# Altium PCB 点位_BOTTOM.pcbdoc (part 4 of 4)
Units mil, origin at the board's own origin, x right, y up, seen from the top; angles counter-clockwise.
Board outline 5102.8 x 4152 mil, 8 copper layers (Top Layer, GND1, 内层2, VCC, 内层4, Inner5, GND2, Bottom Layer); 209 components, 325 nets, 527 pads, 1119 vias.
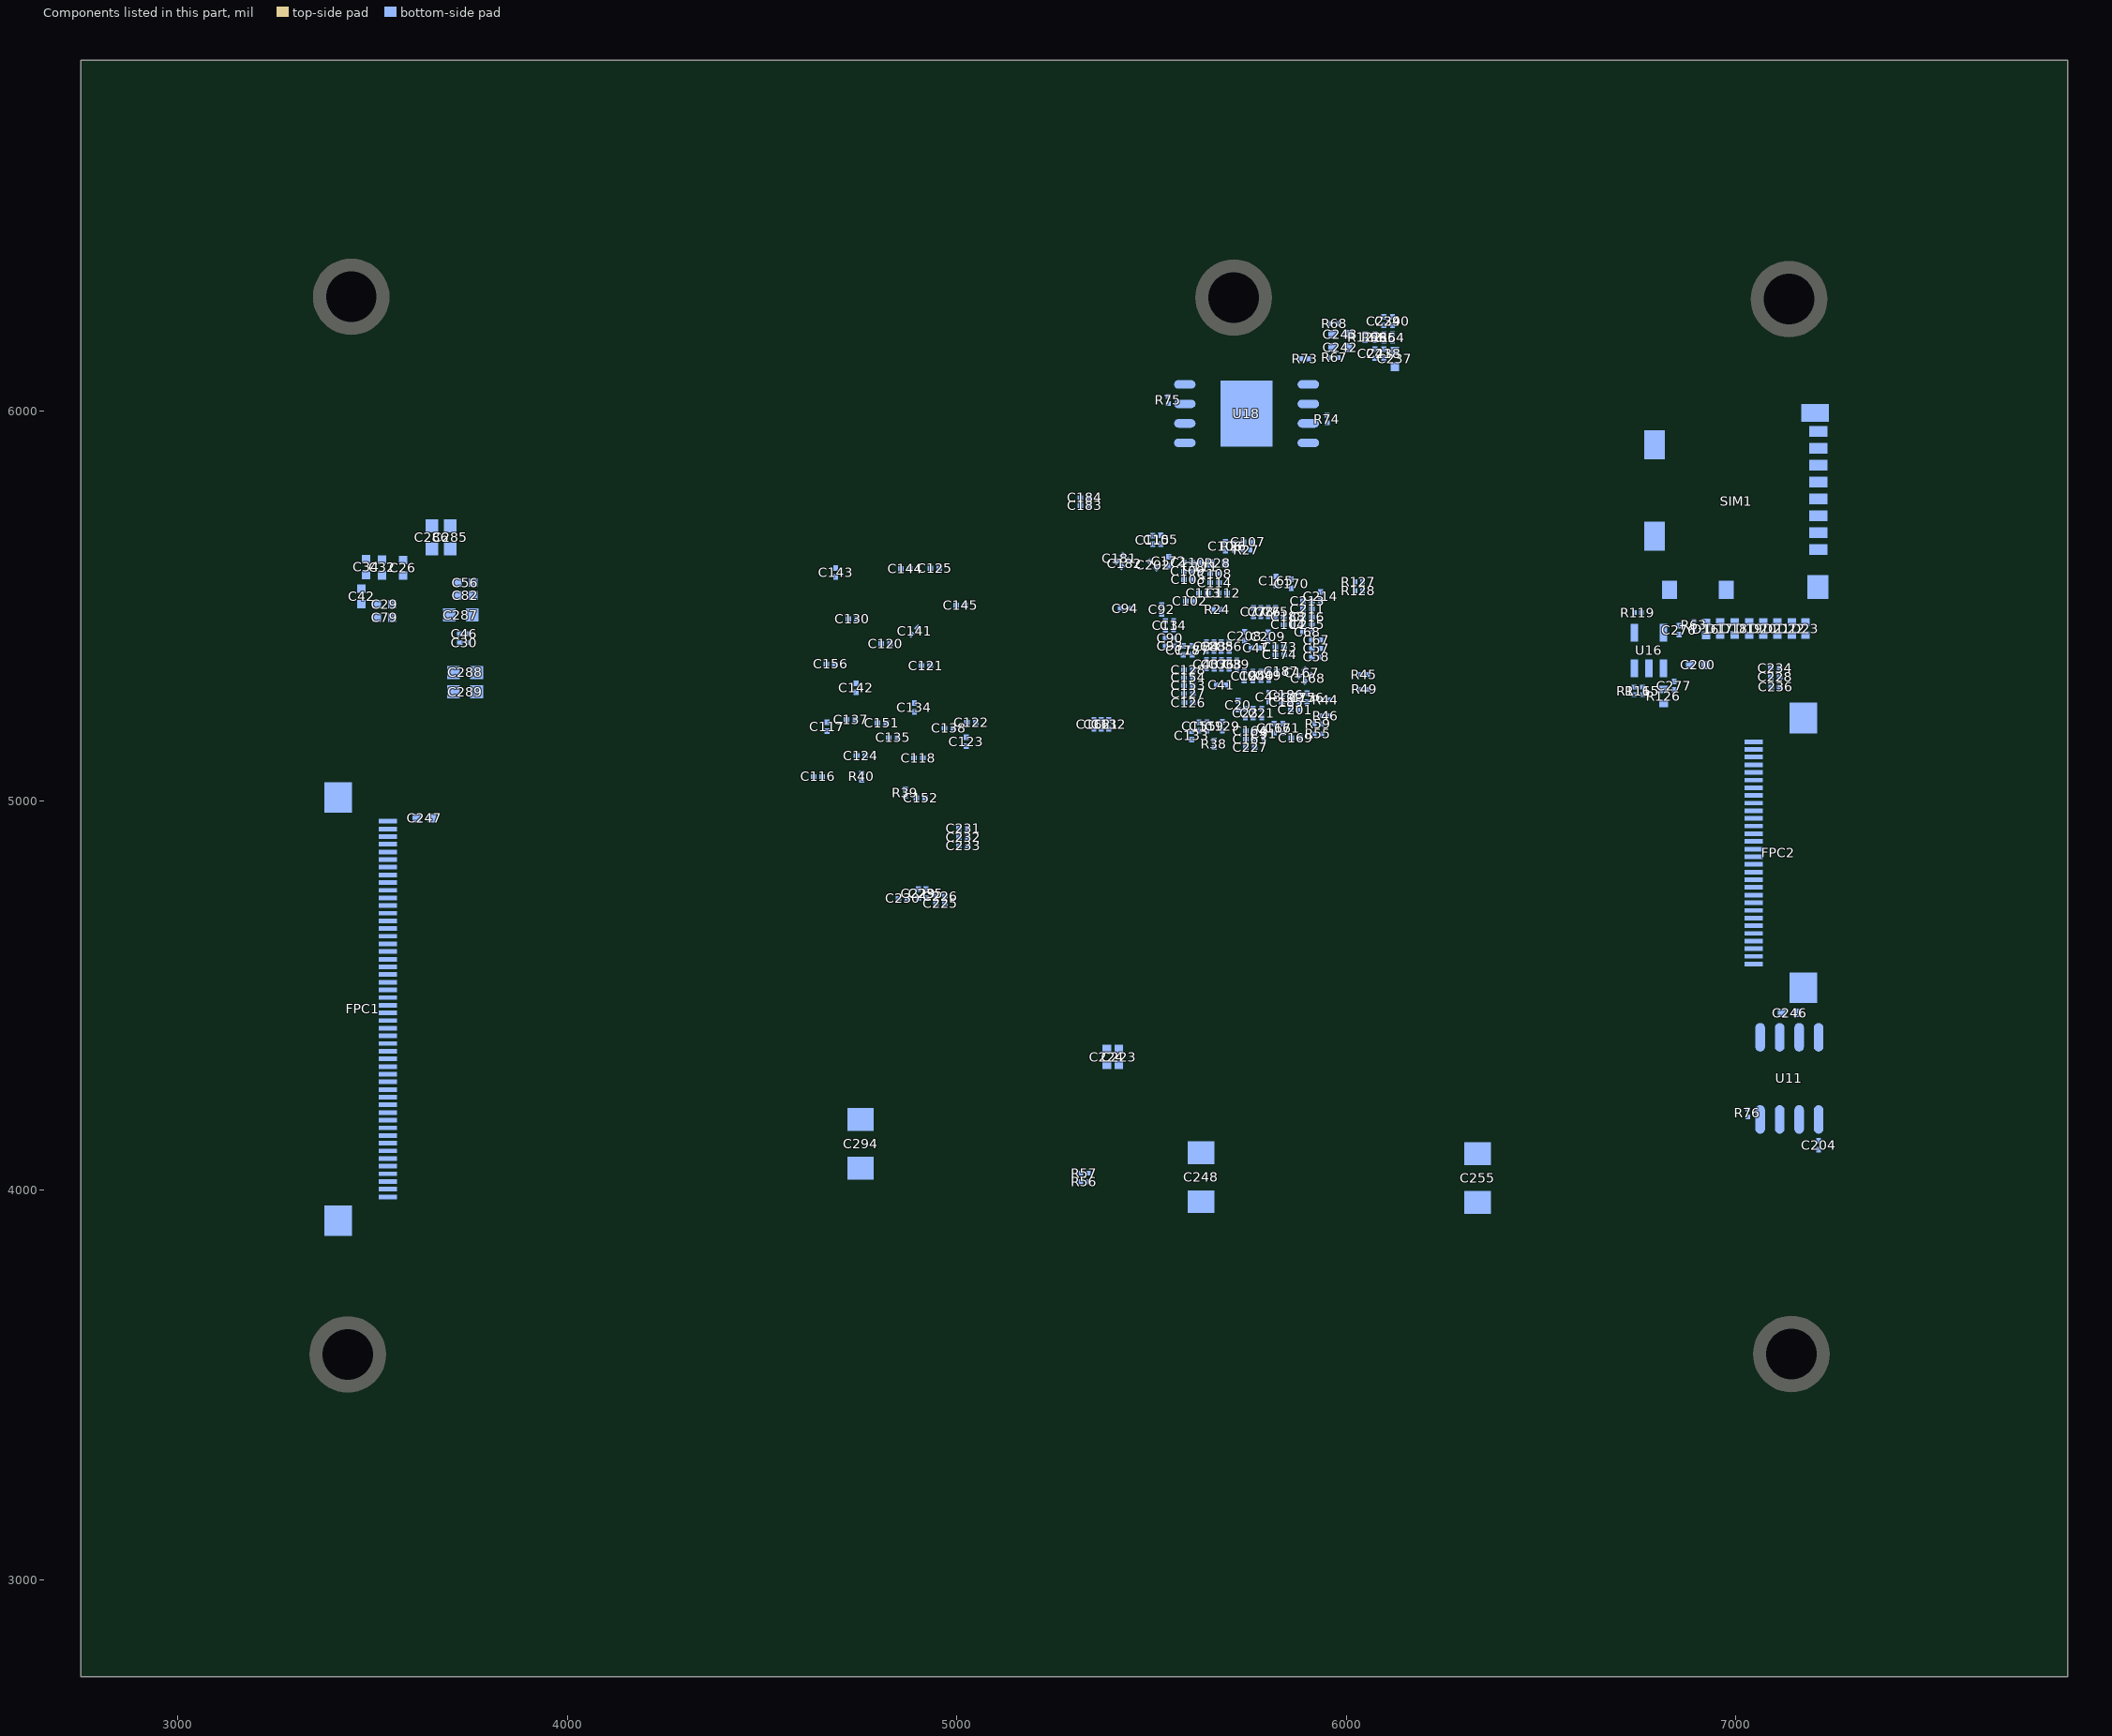
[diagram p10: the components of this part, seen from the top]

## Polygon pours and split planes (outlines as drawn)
GND on 内层2 (solid, remove dead copper): 3007.34,3040 7565.34,3040 7565.34,6640 3007.34,6640
GND on GND1 (solid, remove dead copper): 3000,3052 7558,3052 7558,6652 3000,6652
GND on VCC (solid, remove dead copper): 3012.8,3034 7570.8,3034 7570.8,6634 3012.8,6634
GND on 内层4 (solid, remove dead copper): 3020.8,3025 7578.8,3025 7578.8,6625 3020.8,6625
GND on Inner5 (solid, remove dead copper): 3027.27,3017.38 7585.27,3017.38 7585.27,6617.38 3027.27,6617.38
GND on GND2 (solid, remove dead copper): 3034.8,3010 7592.8,3010 7592.8,6610 3034.8,6610
GND on Bottom Layer (solid, remove dead copper, pour order 36): 3044.8,3000 7602.8,3000 7602.8,6600 3044.8,6600
GND on GND1 (solid, remove dead copper): 5704.72,5249.97 5648.72,5249.97 5636.72,5261.97 5636.72,5357.97 5604.72,5389.97 5361.72,5389.97 5107.72,5643.97 4598.72,5643.97 4578.72,5623.97 4578.72,5014.97 4694.72,4898.97 5650.72,4898.97 5715.72,4963.97 5715.72,5238.97
GND on GND2 (solid, remove dead copper): 5704.24,5250.47 5648.24,5250.47 5636.24,5262.47 5636.24,5358.47 5604.24,5390.47 5361.24,5390.47 5107.24,5644.47 4598.24,5644.47 4578.24,5624.47 4578.24,5015.47 4694.24,4899.47 5650.24,4899.47 5715.24,4964.47 5715.24,5239.47
GND on GND1 (solid, remove dead copper): 5704.66,5251.03 5648.66,5251.03 5636.66,5263.03 5636.66,5359.03 5604.66,5391.03 5361.66,5391.03 5107.66,5645.03 4598.66,5645.03 4578.66,5625.03 4578.66,5016.03 4694.66,4900.03 5650.66,4900.03 5715.66,4965.03 5715.66,5240.03
GND on VCC (solid, remove dead copper): 5705.22,5250.47 5649.22,5250.47 5637.22,5262.47 5637.22,5358.47 5605.22,5390.47 5362.22,5390.47 5108.22,5644.47 4599.22,5644.47 4579.22,5624.47 4579.22,5015.47 4695.22,4899.47 5651.22,4899.47 5716.22,4964.47 5716.22,5239.47
DCDC3 on 内层4 (solid, remove dead copper): 5704.54,5249.47 5648.54,5249.47 5636.54,5261.47 5636.54,5357.47 5616.54,5377.47 5366.54,5377.47 5102.54,5641.47 4596.54,5641.47 4578.54,5623.47 4578.54,5014.47 4694.54,4898.47 5650.54,4898.47 5715.54,4963.47 5715.54,5238.47
BLDO2 on Bottom Layer (solid, remove dead copper, pour order 10): 5023.72,4994.97 5080.19,5051.44 5080.19,5582.5 5026.72,5635.97 4634.21,5635.97 4582.46,5584.22 4582.46,5040.29 4627.77,4994.97
323-DCDC1/2 on 内层2 (solid, remove dead copper): 5657.73,5366.51 5657.73,5263.51 5682.23,5239 5775.8,5239 5789.8,5253 5789.8,5444.25 5390.05,5844 4587.8,5844 4392.8,5649 4392.8,5534 4128.8,5270 4128.8,5083 4178.8,5033 4235.8,5033 4318.8,5116 4318.8,5220 4552.8,5454 4552.8,5597 4617.8,5662 5196.8,5662 5470.8,5388 5636.23,5388
PS on 内层2 (solid, remove dead copper): 3585.81,5664.28 3834.15,5664.28 3902.8,5595.63 3902.8,5393 4079.8,5216 4079.8,5080 4047.8,5048 3919.8,5048 3723.8,5244 3526.8,5244 3445.8,5325 3445.8,5611.07 3488.27,5653.53 3575.06,5653.53
323-DCDC3 on VCC (solid, remove dead copper): 5715.8,5464 5715.8,5425 5695.8,5405 5585.8,5405 5584.8,5406 5377.8,5406 5125.8,5658 4571.8,5658 4196.51,5282.71 4031.64,5282.71 3979.8,5334.55 3979.8,5395 4068.8,5484 4176.8,5484 4518.8,5826 5197.63,5826 5510.68,5512.95 5666.85,5512.95
DCDC3 on 内层4 (solid, remove dead copper): 3730.37,5739 3730.37,5637.28 3748.65,5619 3827.8,5619 3909.8,5537 3909.8,5502 4014.84,5396.97 4590.72,5396.97 4659.47,5465.72 4659.47,5641 4092.8,5641 3973.8,5760 3882.8,5760 3850.8,5792 3783.37,5792
DCDC2 on 内层4 (solid, remove dead copper): 5625.8,5411.39 5625.8,5413 5370.8,5413 5114.8,5669 4108.8,5669 3983.8,5794 3892.8,5794 3867.8,5819 3732.8,5819 3684.8,5771 3684.8,5725 3667.8,5708 3558.8,5708 3532.8,5734 3532.8,5840 3623.8,5931 4126.31,5931 4220.31,5837 5450.8,5837 5889.8,5398 5912.8,5398 5924.8,5386 5924.8,5350 5830.8,5256 5805.8,5256 5794.8,5267 5773.8,5267 5763.8,5277 5763.8,5318.66 5753.71,5328.76 5708.43,5328.76
DCDC1 on Inner5 (solid, remove dead copper): 5729.8,5331 5729.8,5280 5713.8,5264 5674.77,5264 5641.8,5296.96 5641.8,5350.19 5579.4,5412.59 5393.21,5412.59 5140.8,5665 4605.8,5665 4333.8,5393 4029.8,5393 3856.8,5220 3767.06,5220 3723.06,5264 3723.06,5369.09 3914.98,5561 4191.8,5561 4496.8,5866 5117.8,5866 5227.8,5756 5370.45,5756 5728.8,5397.65 5728.8,5332
GND on Bottom Layer (solid, remove dead copper, pour order 38): 5900.8,6146 5900.8,6139 5902.8,6137 5902.8,6135 5905.8,6132 5905.8,6141

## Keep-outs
内层2:
  region: 5628.17,4988.43 5556.72,4916.97 4948.89,4916.97 4850.39,5015.47 4613.16,5015.47 4610.9,5017.73 4610.9,5604.71 4632.16,5625.97 5132.72,5625.97 5366.72,5391.97 5398.72,5391.97 5480.72,5309.97 5568.72,5309.97 5628.17,5250.52
Inner5:
  region: 5701.72,5157.93 5681.41,5178.25 5479.15,5178.25 5463.42,5193.97 5463.42,5235.24 5471.66,5243.47 5531.56,5243.47 5560.72,5272.63 5560.72,5305.97 5517.44,5349.26 5504.25,5349.26 5465.53,5387.97 5367.72,5387.97 5115.72,5639.97 4620.84,5639.97 4582.09,5601.22 4582.09,5497.35 4579.72,5494.97 4579.72,5057.97 4719.72,4917.97 5645.17,4917.97 5701.72,4974.52
Board Outline Layer:
  lines w10: 3321.8,3578.11 ccw(c3439.91,3578.11) 3439.91,3460 7140.7,3460 ccw(c7140.7,3578.11) 7258.81,3578.11 7258.81,6294.65 ccw(c7140.7,6294.65) 7140.7,6412.76 3439.91,6412.76 ccw(c3439.91,6294.65) 3321.8,6294.65 3321.8,3578.11
Multi-Layer:
  region: 5837.51,4256.39 6050.11,4256.39 6167.34,4139.16 6281.8,4139.16 6281.8,3458.89 5651.91,3458.89 5651.8,3459 5651.8,4139.16 5720.28,4139.16
  region: 6555.76,4255.69 6768.36,4255.69 6885.59,4138.46 7000.05,4138.46 7000.05,3458.19 6370.16,3458.19 6370.05,3458.31 6370.05,4138.46 6438.53,4138.46

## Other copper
内层2:
  drawing of 214 lines, arcs and shapes, not listed
VCC:
  region net GM1_DVDDRG: 3510.49,5559.03 3467.45,5516 3447.8,5516 3427.8,5536 3427.8,5558.59 3464.22,5595 3496.73,5595 3510.49,5581.24
  region net ALDO3: 3535.27,5320.46 3531.03,5324.7 3530.42,5324.18 3529.75,5323.78 3529.04,5323.47 3528.29,5323.25 3527.51,5323.09 3525.9,5322.91 3525.08,5322.86 3533.43,5314.51 3533.56,5316.14 3533.66,5316.94 3533.82,5317.72 3534.04,5318.47 3534.35,5319.18 3534.75,5319.85
  region net USB0-DP: 6306.3,5223.37 6301.3,5223.37 6301.23,5222.49 6301.01,5221.75 6300.67,5221.12 6300.24,5220.55 6299.15,5219.47 6297.9,5218.21 6309.71,5218.21 6308.46,5219.47 6307.37,5220.55 6306.93,5221.12 6306.6,5221.75 6306.38,5222.49
  region net USB0-DM: 6286.3,5220.72 6281.3,5220.72 6281.23,5219.82 6281.01,5219.04 6280.67,5218.35 6280.24,5217.72 6279.72,5217.12 6277.9,5215.21 6289.71,5215.21 6287.88,5217.12 6287.37,5217.72 6286.93,5218.35 6286.6,5219.04 6286.38,5219.82
  region net GM1_DVDDRG: 6816.52,4253 6816.52,4263 6814.24,4262.9 6813.56,4262.9 6812.9,4262.97 6812.27,4263.14 6811.64,4263.44 6811.01,4263.91 6811.01,4252.09 6811.64,4252.56 6812.27,4252.86 6812.9,4253.03 6813.56,4253.1 6814.24,4253.1
  region net FEL: 5946.6,5398.16 5946.6,5392.16 5947.4,5392.1 5948.16,5391.91 5948.88,5391.63 5949.56,5391.25 5950.22,5390.81 5951.49,5389.8 5952.11,5389.26 5952.11,5401.07 5950.87,5400 5950.22,5399.51 5949.56,5399.07 5948.88,5398.7 5948.16,5398.41 5947.4,5398.23
  region net PE12: 6060.81,5761.83 6063.64,5759.01 6064.4,5759.65 6065.14,5760.04 6065.88,5760.23 6066.64,5760.29 6068.31,5760.18 6069.25,5760.13 6070.3,5760.14 6061.94,5768.49 6061.93,5767.45 6062.05,5765.64 6062.09,5764.84 6062.08,5764.46 6062.04,5764.08 6061.96,5763.71 6061.84,5763.34 6061.67,5762.97 6061.45,5762.6 6061.16,5762.22
  region net PE8: 6149.81,5760.83 6152.64,5758.01 6153.4,5758.65 6154.14,5759.04 6154.88,5759.23 6155.64,5759.29 6157.31,5759.18 6158.25,5759.13 6159.3,5759.14 6150.94,5767.49 6150.93,5766.45 6151.05,5764.64 6151.09,5763.84 6151.08,5763.46 6151.04,5763.08 6150.96,5762.71 6150.84,5762.34 6150.67,5761.97 6150.45,5761.6 6150.16,5761.22
  region net PE7: 6178.8,5757.28 6182.8,5757.28 6182.89,5758.27 6183.14,5759.08 6183.52,5759.74 6184.02,5760.31 6185.27,5761.41 6185.98,5762.04 6186.71,5762.79 6174.9,5762.79 6175.63,5762.04 6176.99,5760.85 6177.58,5760.31 6177.85,5760.03 6178.08,5759.74 6178.29,5759.42 6178.47,5759.08 6178.61,5758.7 6178.72,5758.27 6178.78,5757.8
  region net PE5: 6129.08,5712 6129.08,5708 6129.75,5707.96 6130.47,5707.86 6131.23,5707.69 6132,5707.46 6132.74,5707.18 6133.44,5706.86 6134.07,5706.49 6134.6,5706.09 6134.6,5717.91 6133.97,5717.23 6132.7,5715.39 6132.05,5714.4 6131.37,5713.48 6130.65,5712.72 6129.89,5712.19
  region net PE6: 6153.81,5704.83 6156.64,5702.01 6157.19,5702.47 6157.82,5702.88 6158.52,5703.24 6159.26,5703.53 6160.03,5703.77 6160.81,5703.95 6161.57,5704.07 6162.3,5704.14 6153.94,5712.49 6153.96,5711.65 6154.36,5708.44 6154.44,5707.35 6154.41,5706.35 6154.22,5705.49
  region net PE1: 6176.64,5720.99 6173.81,5718.17 6174.45,5717.4 6174.84,5716.66 6175.04,5715.92 6175.09,5715.16 6174.98,5713.5 6174.93,5712.55 6174.94,5711.51 6183.3,5719.86 6182.25,5719.87 6180.44,5719.75 6179.64,5719.71 6179.26,5719.73 6178.88,5719.77 6178.51,5719.84 6178.14,5719.96 6177.77,5720.13 6177.4,5720.35 6177.02,5720.64
  region net CLDO3: 7116.92,5497.44 7109.85,5504.52 7108.31,5502.83 7107.82,5502.35 7107.31,5501.93 7106.74,5501.6 7106.08,5501.37 7105.31,5501.26 7113.66,5492.91 7113.78,5493.68 7114.01,5494.34 7114.34,5494.91 7114.75,5495.42 7115.23,5495.9
  region net GM1_DVDDRG: 7014.08,4159 7014.08,4149 7016.37,4149.1 7017.05,4149.1 7017.7,4149.03 7018.34,4148.86 7018.97,4148.56 7019.6,4148.09 7019.6,4159.91 7018.97,4159.44 7018.34,4159.14 7017.7,4158.97 7017.05,4158.9 7016.37,4158.9
  region net GM1_DVDDRG: 3499.08,5698.88 3499.08,5692.88 3499.88,5692.69 3500.64,5692.18 3501.36,5691.43 3502.04,5690.53 3503.98,5687.76 3504.59,5687.09 3504.59,5698.91 3503.88,5698.38 3503.25,5698.14 3502.67,5698.1 3502.1,5698.21 3500.81,5698.63 3500.02,5698.81
  region net AP-RESET: 3958.8,5064.28 3964.8,5064.28 3964.87,5065.08 3965.05,5065.84 3965.34,5066.55 3965.71,5067.24 3966.15,5067.9 3967.17,5069.17 3967.71,5069.79 3955.9,5069.79 3956.96,5068.54 3957.46,5067.9 3957.9,5067.24 3958.27,5066.55 3958.55,5065.84 3958.74,5065.08
  region net USB0-DP: 6697.04,6014.77 6700.57,6011.23 6701.23,6011.79 6701.87,6012.12 6702.51,6012.28 6703.15,6012.31 6704.57,6012.19 6705.39,6012.13 6706.3,6012.14 6697.94,6020.49 6697.93,6019.58 6698.07,6018.03 6698.11,6017.35 6698.08,6016.7 6697.92,6016.07 6697.59,6015.43
  region net USB0-DM: 6688.04,6011.23 6691.57,6014.77 6691.02,6015.43 6690.68,6016.07 6690.53,6016.7 6690.49,6017.35 6690.62,6018.77 6690.67,6019.58 6690.66,6020.49 6682.31,6012.14 6683.22,6012.13 6684.77,6012.26 6685.45,6012.31 6686.1,6012.28 6686.73,6012.12 6687.37,6011.79
  region net GM1_DVDDRG: 5292.8,4480.31 5302.8,4480.31 5302.69,4482.59 5302.69,4483.27 5302.76,4483.92 5302.93,4484.55 5303.23,4485.18 5303.69,4485.81 5291.92,4485.81 5292.38,4485.18 5292.68,4484.55 5292.85,4483.92 5292.92,4483.27 5292.91,4482.59
  region net VDD-DNRFB: 5631.26,5430.19 5638.33,5423.12 5639.87,5424.81 5640.34,5425.29 5640.85,5425.7 5641.42,5426.03 5642.07,5426.26 5642.85,5426.38 5634.52,5434.7 5634.4,5433.93 5634.17,5433.28 5633.85,5432.71 5633.43,5432.2 5632.95,5431.73
  region net VDD-DNRFB: 3936.9,5272.02 3929.82,5279.09 3928.29,5277.4 3927.81,5276.92 3927.31,5276.51 3926.74,5276.18 3926.08,5275.95 3925.31,5275.83 3933.64,5267.51 3933.75,5268.28 3933.98,5268.94 3934.31,5269.5 3934.72,5270.01 3935.2,5270.49
  region net CLDO3: 5566.49,6055.13 5559.42,6062.2 5557.88,6060.51 5557.41,6060.02 5556.9,6059.61 5556.33,6059.28 5555.68,6059.05 5554.91,6058.94 5563.23,6050.61 5563.35,6051.38 5563.58,6052.04 5563.91,6052.61 5564.32,6053.11 5564.8,6053.59
  region net AP-RESET: 3588.3,5402.31 3593.3,5402.31 3593.33,5402.89 3593.4,5403.4 3593.52,5403.84 3593.68,5404.22 3593.88,5404.56 3594.11,5404.85 3594.38,5405.12 3594.67,5405.37 3595.7,5406.1 3596.47,5406.66 3596.87,5406.99 3597.28,5407.37 3597.69,5407.81 3585.92,5407.81 3586.36,5407.26 3586.79,5406.63 3587.2,5405.95 3587.56,5405.23 3587.86,5404.49 3588.1,5403.74 3588.25,5403.01
  region net AP-NMI: 3609.8,5401.31 3615.8,5401.31 3615.96,5402.02 3616.39,5402.76 3617.03,5403.5 3617.79,5404.23 3620.13,5406.25 3620.69,5406.81 3608.92,5406.81 3609.38,5406.18 3609.68,5405.55 3609.85,5404.92 3609.92,5404.27 3609.91,5403.59
  region net AP-NMI: 3608.66,5420.97 3605.83,5418.14 3606.47,5417.38 3606.86,5416.64 3607.06,5415.9 3607.11,5415.15 3607.01,5413.49 3606.95,5412.55 3606.97,5411.51 3615.29,5419.83 3614.25,5419.85 3612.45,5419.73 3611.66,5419.69 3611.27,5419.71 3610.9,5419.75 3610.53,5419.82 3610.16,5419.94 3609.79,5420.11 3609.42,5420.33 3609.05,5420.62
  region net AP-NMI: 3610.83,5582.86 3613.66,5580.03 3614.42,5580.67 3615.16,5581.06 3615.9,5581.25 3616.66,5581.31 3618.31,5581.2 3619.25,5581.15 3620.29,5581.17 3611.97,5589.49 3611.95,5588.45 3612.08,5586.65 3612.11,5585.85 3612.1,5585.47 3612.06,5585.1 3611.98,5584.73 3611.86,5584.36 3611.69,5583.99 3611.47,5583.62 3611.19,5583.24
  region net ALDO3: 3824.87,5419.68 3820.62,5415.44 3821.14,5414.83 3821.54,5414.16 3821.85,5413.46 3822.07,5412.71 3822.23,5411.93 3822.41,5410.33 3822.47,5409.51 3830.79,5417.83 3829.17,5417.96 3828.37,5418.07 3827.59,5418.23 3826.85,5418.45 3826.14,5418.76 3825.48,5419.16
  region net AP-RESET: 3886.12,5202.5 3886.12,5197.5 3886.75,5197.57 3887.46,5197.74 3889.01,5198.19 3889.77,5198.37 3890.48,5198.45 3891.11,5198.38 3891.61,5198.11 3891.61,5209.89 3891.23,5209.5 3890.89,5209.04 3890.57,5208.52 3889.97,5207.36 3888.83,5204.91 3888.53,5204.35 3888.21,5203.84 3887.86,5203.39 3887.48,5203.02 3887.07,5202.74 3886.61,5202.56
  region net FEL: 4083.49,5789 4083.49,5795 4082.69,5795.06 4081.94,5795.25 4081.22,5795.53 4080.54,5795.9 4079.88,5796.34 4078.61,5797.35 4078,5797.89 4078,5786.11 4079.24,5787.17 4079.88,5787.66 4080.54,5788.1 4081.22,5788.47 4081.94,5788.75 4082.69,5788.94
  region net AP-NMI: 3615.8,5360.69 3609.8,5360.69 3609.74,5359.89 3609.56,5359.14 3609.27,5358.42 3608.9,5357.74 3608.46,5357.07 3607.45,5355.81 3606.92,5355.19 3618.69,5355.19 3617.63,5356.43 3617.14,5357.07 3616.71,5357.74 3616.34,5358.42 3616.05,5359.14 3615.87,5359.89
  region net CPUX-RX: 6771,6104.12 6775,6104.12 6775.09,6105.11 6775.33,6105.9 6775.72,6106.56 6776.21,6107.14 6777.46,6108.24 6778.16,6108.86 6778.89,6109.61 6767.11,6109.61 6767.84,6108.86 6769.2,6107.68 6769.79,6107.14 6770.05,6106.86 6770.28,6106.56 6770.49,6106.25 6770.67,6105.9 6770.81,6105.53 6770.91,6105.11 6770.98,6104.64
  region net CPUX-TX: 6633.91,6113.36 6633.91,6109.36 6634.9,6109.28 6635.69,6109.03 6636.35,6108.65 6636.93,6108.15 6638.03,6106.9 6638.65,6106.2 6639.4,6105.48 6639.4,6117.25 6638.65,6116.53 6637.47,6115.17 6636.93,6114.58 6636.65,6114.32 6636.35,6114.08 6636.04,6113.87 6635.69,6113.7 6635.32,6113.56 6634.9,6113.45 6634.43,6113.39
  region net CPUX-RX: 6273.8,5262.69 6269.8,5262.69 6269.72,5261.7 6269.47,5260.9 6269.09,5260.24 6268.59,5259.66 6267.34,5258.57 6266.64,5257.94 6265.92,5257.19 6277.69,5257.19 6276.97,5257.94 6275.61,5259.12 6275.02,5259.66 6274.76,5259.94 6274.52,5260.24 6274.31,5260.55 6274.14,5260.9 6274,5261.28 6273.89,5261.7 6273.83,5262.17
  region net CPUX-TX: 6260.77,5269.14 6257.95,5271.97 6257.18,5271.33 6256.45,5270.94 6255.71,5270.75 6254.95,5270.69 6253.29,5270.8 6252.35,5270.85 6251.31,5270.83 6259.64,5262.51 6259.65,5263.55 6259.53,5265.35 6259.5,5266.15 6259.51,5266.53 6259.55,5266.9 6259.63,5267.27 6259.75,5267.64 6259.91,5268.01 6260.14,5268.38 6260.42,5268.76
  region net GM1_DVDDRG: 6075.12,4265 6075.12,4255 6075.93,4255.19 6076.69,4255.7 6077.4,4256.38 6078.72,4257.78 6079.36,4258.26 6079.98,4258.41 6080.61,4258.11 6080.61,4269.89 6080.05,4269.33 6078.04,4266.99 6077.3,4266.22 6076.56,4265.59 6075.83,4265.16
  region net CLDO2: 5758.8,5099.31 5768.8,5099.31 5768.69,5101.59 5768.69,5102.27 5768.76,5102.92 5768.93,5103.55 5769.23,5104.18 5769.69,5104.81 5757.92,5104.81 5758.38,5104.18 5758.68,5103.55 5758.85,5102.92 5758.92,5102.27 5758.91,5101.59
  region net CLDO2: 3835.3,5594.69 3825.3,5594.69 3825.41,5592.41 3825.42,5591.73 3825.35,5591.08 3825.18,5590.45 3824.88,5589.82 3824.42,5589.19 3836.19,5589.19 3835.73,5589.82 3835.43,5590.45 3835.26,5591.08 3835.19,5591.73 3835.19,5592.41
  region net AP-RESET: 4208.12,4994 4208.12,4988 4208.91,4987.94 4209.67,4987.75 4210.38,4987.47 4211.07,4987.1 4211.73,4986.66 4212.99,4985.65 4213.61,4985.11 4213.61,4996.89 4212.37,4995.83 4211.73,4995.34 4211.07,4994.9 4210.38,4994.53 4209.67,4994.25 4208.91,4994.06
  region net GM1_DVDDRG: 5900.8,4500.81 5910.8,4500.81 5910.69,4503.09 5910.69,4503.77 5910.76,4504.42 5910.93,4505.05 5911.23,4505.68 5911.69,4506.31 5899.92,4506.31 5900.38,4505.68 5900.68,4505.05 5900.85,4504.42 5900.92,4503.77 5900.91,4503.09
  region net GM1_DVDDRG: 6403.8,4440.21 6380.05,4421.54 ccw(c6431.72,4473.22) 6401.08,4406.87 6418.65,4419 ccw(c6351.12,4387.53)
  region net GM1_DVDDRG: 6541.59,4231.57 6545.64,4235.43 6548.77,4238.09 6551.42,4240.09 6553.55,4241.5 6555.16,4242.43 6556.78,4243.25 6558.39,4243.94 6559.47,4244.32 6560.55,4244.64 6561.62,4244.88 6562.7,4245.06 6563.77,4245.16 6564.84,4245.18 6565.9,4245.13 6566.96,4244.98 6568.02,4244.75 6569.07,4244.43 6570.11,4244.01 6571.14,4243.49 6572.17,4242.88 6573.19,4242.16 6574.2,4241.33 6575.2,4240.39 6596.41,4261.61 6594.54,4263.6 6592.78,4265.73 6591.14,4267.98 6589.6,4270.33 6587.72,4273.63 6586.02,4277.09 6584.5,4280.68 6582.84,4285.32 6581.43,4290.1 6580.07,4295.93 6579.05,4301.82 6578.35,4307.68 6577.89,4314.37 6577.8,4319 6547.8,4319 6547.71,4316.19 6547.45,4313.21 6546.85,4309.03 6545.72,4303.53 6544.2,4297.81 6541.93,4290.79 6539.23,4283.76 6536.17,4276.88 6532.81,4270.31 6529.84,4265.2 6526.75,4260.51 6524.22,4257.13 6522.3,4254.84 6520.38,4252.79
  region net GM1_DVDDRG: 6819.34,4234.67 6820.23,4264.66 6789.8,4250.55 6729.8,4266
  region net GM1_DVDDRG: 6840.37,4234.05 6845.1,4233.78 6850.6,4233.17 6856.88,4232.14 6863.31,4230.74 6870.38,4228.81 6876.82,4226.69 6883.11,4224.24 6888.63,4221.74 6893.38,4219.27 6897.37,4216.92 6900.67,4214.73 6903.76,4212.44 6906.21,4210.38 6908.12,4208.61 6908.48,4208.25 6915.55,4215.32 6914.52,4216.25 6911.46,4218.59 6899.22,4227.24 6896.67,4229.2 6895.33,4230.35 6894.79,4230.86 6894.35,4231.33 6894.02,4231.75 6893.81,4232.11 6893.72,4232.42 6893.77,4232.67 6893.96,4232.85 6894.3,4232.96 6894.8,4233 6894.8,4263 6841.26,4264.03
  region net GM1_DVDDRG: 5658.48,4365.32 5665.94,4372.41 5674.03,4379.35 5681.99,4385.5 5689.64,4390.82 5697.57,4395.74 5704.99,4399.8 5711.79,4403.05 5717.93,4405.58 5723.34,4407.5 5728.78,4409.1 5733.46,4410.22 5738.14,4411.08 5742.82,4411.66 5746.7,4411.93 5749.8,4412 5749.8,4442 5699.8,4427 5623.13,4400.68
  region net GM1_DVDDRG: 5411.8,4208 5391.8,4208 ccw(c5186.23,4208) 5326.8,4358 5476.8,4358 ccw(c5617.38,4208)
  region net GM1_DVDDRG: 3515.45,6090.29 3518.69,6093.36 3522.92,6096.96 3528.29,6101.01 3534.07,6104.9 3541.13,6109.13 3549.55,6113.61 3559.4,6118.18 3570.65,6122.71 3582.16,6126.64 3593.74,6129.95 3605.21,6132.59 3615.37,6134.36 3624.19,6135.42 3631.68,6135.91 3636.16,6136 3636.16,6186 3634.45,6186.05 3631.81,6186.29 3630.06,6186.56 3628.34,6186.91 3626.7,6187.35 3625.15,6187.87 3623.74,6188.47 3623.1,6188.8 3622.49,6189.15 3621.94,6189.51 3621.44,6189.89 3621,6190.29 3620.61,6190.71 3620.29,6191.14 3620.04,6191.59 3619.87,6192.06 3619.76,6192.55 3619.74,6193.04 3619.8,6193.56 3619.95,6194.09 3620.2,6194.63 3620.53,6195.19 3620.97,6195.77 3621.51,6196.36
  region net ALDO4: 5686.42,5559.82 5683.31,5544.82 ccw(c5683.31,5582.07) 5696.06,5547.07 5696.06,5557.57 ccw(c5686.42,5538.03)
  region net ALDO4: 5649.3,5377.39 5649.27,5377.82 5649.02,5379.06 5647.49,5384.83 5647.22,5386.07 5647.17,5386.49 5647.2,5386.75 5647.3,5386.83 5647.5,5386.7 5658.11,5397.3 5647.11,5397.7 5618.39,5390.2 5629,5379.59 5629.39,5379.93 5629.81,5380.2 5630.24,5380.39 5630.68,5380.51 5631.13,5380.56 5631.57,5380.54 5632,5380.47 5632.41,5380.33 5632.8,5380.13 5633.16,5379.88 5633.48,5379.58 5633.76,5379.23 5633.99,5378.84 5634.16,5378.4 5634.27,5377.91 5634.3,5377.39
  region net GM1_DVDDRG: 5862.5,5077.7 5873.11,5088.3 cw(c5875.58,5090.77) 5872.78,5092.87 5855.94,5080.01 cw(c5856.79,5071.99)
  region net GM1_DVDDRG: 5867.41,5493.79 5872.71,5509.7 ccw(c5857.3,5494.29) 5864.3,5514.93 5858.39,5505.98 ccw(c5903.56,5529.94)
  region net CLDO3: 7130.55,5511.08 7112.87,5500.47 7095.87,5469.33 7081.73,5483.47 7102.27,5489.86 7123.48,5518.15
  region net CLDO3: 4860.36,4496.34 4863.83,4499.63 4868.42,4503.53 4873.4,4507.3 4878.71,4510.87 4884.27,4514.17 4889.05,4516.67 4893.92,4518.89 4898.85,4520.8 4902.8,4522.08 4906.73,4523.11 4910.64,4523.87 4913.53,4524.25 4916.39,4524.46 4918.26,4524.5 4918.26,4549.5 4916.76,4549.55 4915.31,4549.69 4913.9,4549.91 4912.53,4550.23 4911.21,4550.63 4909.93,4551.11 4908.7,4551.66 4907.51,4552.29 4906.37,4552.99 4905.28,4553.76 4904.23,4554.6 4903.23,4555.49 4902.28,4556.45 4901.37,4557.46 4900.51,4558.53 4899.31,4560.22 4898.21,4562.02 4897.23,4563.91 4896.35,4565.89 4895.58,4567.93 4894.92,4570.05 4894.37,4572.21 4893.94,4574.42 4893.61,4576.66 4893.41,4578.93 4893.31,4581.21 4893.3,4581.97 4868.3,4581.97 4868.21,4579.01 4867.93,4575.96 4867.29,4571.76 4866.36,4567.44 4864.83,4561.94 4862.92,4556.37 4860.68,4550.81 4857.61,4544.23 4854.19,4537.87 4850.49,4531.83 4847.25,4527.15 4843.91,4522.83 4841.19,4519.7 4839.14,4517.55
  region net GM1_DVDDRG: 5839.02,4415 5838.05,4416.02 5837.15,4417.11 5836.31,4418.25 5835.54,4419.43 5834.82,4420.67 5834.17,4421.94 5833.31,4423.93 5832.58,4425.99 5832,4428.12 5831.56,4430.29 5831.26,4432.49 5831.09,4434.72 5831.07,4436.96 5831.19,4439.19 5831.44,4441.41 5831.84,4443.59 5832.37,4445.73 5833.05,4447.81 5833.87,4449.83 5834.49,4451.13 5835.17,4452.38 5835.92,4453.59 5836.72,4454.76 5837.59,4455.87 5838.53,4456.92 5839.02,4457.43 5817.8,4478.64 5807.2,4446.82 5817.8,4393.79
  region net GM1_DVDDRG: 5827.8,4322 5827.68,4317.34 5827.21,4311.51 5826.39,4305.5 5825.21,4299.4 5823.67,4293.31 5822.12,4288.31 5820.31,4283.44 5818.25,4278.75 5816.41,4275.16 5814.42,4271.75 5812.81,4269.32 5811.12,4267.02 5809.33,4264.87 5807.45,4262.86 5828.66,4241.64 5831.54,4244.71 5838.45,4252.87 5840.47,4255.09 5842.07,4256.65 5843.26,4257.67 5844.06,4258.27 5844.86,4258.79 5845.67,4259.23 5846.48,4259.59 5846.89,4259.74 5847.3,4259.86 5847.71,4259.96 5848.13,4260.04 5848.55,4260.09 5848.97,4260.12 5849.4,4260.11 5849.82,4260.09 5850.26,4260.03 5850.69,4259.94 5851.13,4259.83 5851.57,4259.69 5852.02,4259.51 5852.47,4259.31 5853.39,4258.8 5854.33,4258.16 5855.29,4257.39 5856.27,4256.46 5863.34,4263.54 5861.29,4265.7 5859.85,4267.41 5858.58,4269.09 5857.46,4270.75 5856.5,4272.39 5855.69,4274.02 5855.16,4275.23 5854.71,4276.44 5854.33,4277.65 5853.93,4279.25 5853.63,4280.86 5853.43,4282.47 5853.32,4284.09 5853.31,4286.13 5853.4,4288.19 5853.7,4291.13 5854.54,4296.36 5856.79,4308.9 5857.44,4314.32 5857.75,4318.96 5857.8,4322
  region net CLDO3: 3830.3,5635.5 3830.3,5620.5 ccw(c3830.3,5671.75) 3837.44,5621 3837.44,5635 ccw(c3830.3,5584.25)
  region net CLDO3: 3477.69,5486.75 3463.55,5500.89 3449.41,5472.61 3423.8,5428.34
  region net GM1_DVDDRG: 6062.8,4565 6062.8,4535 6092.8,4550 6122.8,4584
  region net CLDO3: 5669.13,4515.36 5651.45,4497.68 5677.96,4488.84 5704.8,4467.5
  region net GM1_DVDDRG: 6599.22,4482.58 6599.22,4462.58 ccw(c6599.22,4472.58) 6606.36,4465.58 6606.36,4479.58 ccw(c6599.22,4472.58)
内层4:
  region net DCDC3: 3714.34,5600.54 3707.27,5593.46 3708.65,5592.13 3709.05,5591.69 3709.39,5591.22 3709.66,5590.71 3709.85,5590.15 3709.94,5589.51 3718.3,5597.86 3717.65,5597.95 3717.09,5598.14 3716.58,5598.41 3716.12,5598.75 3715.68,5599.15
  region net VDD-SYSFB: 3643.8,5602.72 3633.8,5602.72 3633.91,5600.43 3633.91,5599.75 3633.84,5599.1 3633.66,5598.46 3633.36,5597.84 3632.9,5597.21 3644.71,5597.21 3644.24,5597.84 3643.94,5598.46 3643.77,5599.1 3643.7,5599.75 3643.7,5600.43
  region net PWRON: 3668.26,5399.3 3672.5,5403.54 3671.99,5404.15 3671.58,5404.82 3671.28,5405.53 3671.05,5406.28 3670.9,5407.06 3670.72,5408.67 3670.66,5409.49 3662.31,5401.14 3663.95,5401.01 3664.75,5400.91 3665.53,5400.75 3666.27,5400.53 3666.99,5400.22 3667.65,5399.82
  region net RGMII0-RXD3: 6036.81,4507.32 6039.64,4504.5 6040.4,4505.14 6041.14,4505.53 6041.88,4505.72 6042.64,4505.78 6044.31,4505.67 6045.25,4505.62 6046.3,4505.63 6037.94,4513.98 6037.93,4512.94 6038.05,4511.13 6038.09,4510.33 6038.08,4509.95 6038.04,4509.57 6037.96,4509.2 6037.84,4508.83 6037.67,4508.46 6037.45,4508.09 6037.16,4507.71
  region net RGMII0-RXD2: 6018.8,4502.77 6022.8,4502.77 6022.89,4503.76 6023.14,4504.57 6023.52,4505.23 6024.02,4505.8 6025.27,4506.9 6025.98,4507.53 6026.71,4508.28 6014.9,4508.28 6015.63,4507.53 6016.99,4506.34 6017.58,4505.8 6017.85,4505.52 6018.08,4505.23 6018.29,4504.91 6018.47,4504.57 6018.61,4504.19 6018.72,4503.76 6018.78,4503.29
  region net RGMII0-RXD2: 6005.15,5427.83 6007.98,5430.66 6007.35,5431.23 6006.19,5432.15 6005.69,5432.58 6005.26,5433.05 6004.91,5433.58 6004.67,5434.23 6004.55,5435.03 5996.2,5426.68 5996.72,5426.68 5997.28,5426.75 5997.86,5426.88 5999.08,5427.25 6001.59,5428.1 6002.19,5428.26 6002.77,5428.37 6003.32,5428.43 6003.84,5428.42 6004.32,5428.32 6004.76,5428.13
  region net RGMII0-RXD3: 5983.17,5425.53 5985.99,5428.36 5985.35,5429.13 5984.96,5429.87 5984.77,5430.61 5984.71,5431.37 5984.82,5433.03 5984.87,5433.97 5984.86,5435.02 5976.51,5426.67 5977.55,5426.65 5979.36,5426.78 5980.16,5426.81 5980.54,5426.8 5980.92,5426.76 5981.29,5426.68 5981.66,5426.56 5982.03,5426.4 5982.4,5426.17 5982.78,5425.89
  region net CPUX-RX: 5809.15,5125.42 5806.32,5128.25 5805.56,5127.61 5804.81,5127.22 5804.07,5127.02 5803.31,5126.97 5801.65,5127.07 5800.71,5127.13 5799.66,5127.11 5808.01,5118.76 5808.03,5119.81 5807.9,5121.61 5807.87,5122.41 5807.88,5122.8 5807.92,5123.17 5808,5123.54 5808.12,5123.91 5808.29,5124.28 5808.51,5124.65 5808.79,5125.03
  region net CPUX-TX: 5809.15,5145.09 5806.32,5147.92 5805.56,5147.28 5804.81,5146.89 5804.07,5146.69 5803.31,5146.64 5801.65,5146.75 5800.71,5146.8 5799.66,5146.78 5808.01,5138.43 5808.03,5139.48 5807.9,5141.28 5807.87,5142.08 5807.88,5142.47 5807.92,5142.84 5808,5143.21 5808.12,5143.58 5808.29,5143.95 5808.51,5144.33 5808.79,5144.7
  region net LCD0-D21: 5924.08,5109.21 5927.61,5112.75 5927.03,5113.44 5926.63,5114.14 5926.38,5114.87 5926.24,5115.62 5926.18,5116.41 5926.12,5119.05 5917.77,5110.7 5920.41,5110.64 5921.2,5110.58 5921.96,5110.44 5922.68,5110.19 5923.39,5109.79
  region net HTXCN: 5039.8,4342.87 5035.8,4342.87 5035.72,4341.92 5035.47,4341.21 5035.08,4340.68 5034.58,4340.26 5033.33,4339.46 5032.63,4338.92 5031.9,4338.21 5043.71,4338.21 5043.34,4338.59 5042.98,4338.92 5042.62,4339.21 5041.94,4339.68 5041.02,4340.26 5040.76,4340.47 5040.52,4340.68 5040.32,4340.93 5040.14,4341.21 5040,4341.54 5039.89,4341.92 5039.83,4342.36
  region net HTXCP: 5060.8,4342.87 5056.8,4342.87 5056.72,4341.92 5056.47,4341.21 5056.08,4340.68 5055.58,4340.26 5054.33,4339.46 5053.63,4338.92 5052.9,4338.21 5064.71,4338.21 5064.34,4338.59 5063.98,4338.92 5063.62,4339.21 5062.94,4339.68 5062.02,4340.26 5061.76,4340.47 5061.52,4340.68 5061.32,4340.93 5061.14,4341.21 5061,4341.54 5060.89,4341.92 5060.83,4342.36
  region net HTX0N: 5096.8,4342.87 5092.8,4342.87 5092.72,4341.92 5092.47,4341.21 5092.08,4340.68 5091.58,4340.26 5090.33,4339.46 5089.63,4338.92 5088.9,4338.21 5100.71,4338.21 5100.34,4338.59 5099.98,4338.92 5099.62,4339.21 5098.94,4339.68 5098.02,4340.26 5097.76,4340.47 5097.52,4340.68 5097.32,4340.93 5097.14,4341.21 5097,4341.54 5096.89,4341.92 5096.83,4342.36
  region net HTX0P: 5116.8,4342.87 5112.8,4342.87 5112.72,4341.92 5112.47,4341.21 5112.08,4340.68 5111.58,4340.26 5110.33,4339.46 5109.63,4338.92 5108.9,4338.21 5120.71,4338.21 5120.34,4338.59 5119.98,4338.92 5119.62,4339.21 5118.94,4339.68 5118.02,4340.26 5117.76,4340.47 5117.52,4340.68 5117.32,4340.93 5117.14,4341.21 5117,4341.54 5116.89,4341.92 5116.83,4342.36
  region net HTX1N: 5152.8,4341.87 5148.8,4341.87 5148.72,4340.92 5148.47,4340.21 5148.08,4339.68 5147.58,4339.26 5146.33,4338.46 5145.63,4337.92 5144.9,4337.21 5156.71,4337.21 5156.34,4337.59 5155.98,4337.92 5155.62,4338.21 5154.94,4338.68 5154.02,4339.26 5153.76,4339.47 5153.52,4339.68 5153.32,4339.93 5153.14,4340.21 5153,4340.54 5152.89,4340.92 5152.83,4341.36
  region net HTX1P: 5172.8,4340.87 5168.8,4340.87 5168.68,4340.34 5168.33,4339.83 5167.82,4339.36 5167.22,4338.9 5165.35,4337.62 5164.9,4337.21 5176.71,4337.21 5176.26,4337.62 5174.39,4338.9 5173.78,4339.36 5173.28,4339.83 5172.93,4340.34
  region net HTX2N: 5211.8,4341.87 5207.8,4341.87 5207.72,4340.92 5207.47,4340.21 5207.08,4339.68 5206.58,4339.26 5205.33,4338.46 5204.63,4337.92 5203.9,4337.21 5215.71,4337.21 5215.34,4337.59 5214.98,4337.92 5214.62,4338.21 5213.94,4338.68 5213.02,4339.26 5212.76,4339.47 5212.52,4339.68 5212.32,4339.93 5212.14,4340.21 5212,4340.54 5211.89,4340.92 5211.83,4341.36
  region net HTX2P: 5232.47,4341.87 5228.47,4341.87 5228.38,4340.92 5228.13,4340.21 5227.74,4339.68 5227.25,4339.26 5225.99,4338.46 5225.29,4337.92 5224.56,4337.21 5236.37,4337.21 5236.01,4337.59 5235.64,4337.92 5235.29,4338.21 5234.6,4338.68 5233.69,4339.26 5233.42,4339.47 5233.19,4339.68 5232.98,4339.93 5232.8,4340.21 5232.66,4340.54 5232.55,4340.92 5232.49,4341.36
  region net HTX2P: 6292.39,5181.59 6295.22,5184.41 6294.94,5184.87 6294.86,5185.44 6294.92,5186.09 6295.08,5186.79 6295.48,5188.22 6295.63,5188.89 6295.66,5189.49 6287.31,5181.14 6287.91,5181.18 6288.58,5181.32 6290.01,5181.72 6290.71,5181.88 6291.36,5181.94 6291.93,5181.86
  region net HTX2N: 6295.22,5173.59 6292.39,5176.41 6291.93,5176.14 6291.36,5176.06 6290.71,5176.12 6290.01,5176.28 6288.58,5176.68 6287.91,5176.82 6287.31,5176.86 6295.66,5168.51 6295.63,5169.11 6295.48,5169.78 6295.08,5171.21 6294.92,5171.91 6294.86,5172.56 6294.94,5173.13
  region net HTX1P: 6281.52,5141 6281.52,5145 6280.93,5145.08 6280.42,5145.29 6279.98,5145.63 6279.6,5146.08 6279.26,5146.62 6278.97,5147.23 6278.45,5148.62 6277.73,5150.85 6277.46,5151.57 6277.17,5152.26 6276.83,5152.88 6276.45,5153.44 6276.01,5153.91 6276.01,5142.09 6276.54,5142.37 6277.17,5142.39 6277.87,5142.24 6278.61,5141.97 6280.13,5141.33 6280.85,5141.09
  region net HTX1N: 6280.22,5132.59 6277.39,5135.41 6276.65,5134.8 6275.97,5134.47 6275.33,5134.37 6274.67,5134.42 6273.21,5134.73 6272.33,5134.85 6271.31,5134.86 6279.66,5126.51 6279.68,5127.04 6279.65,5127.53 6279.6,5127.98 6279.45,5128.8 6279.23,5129.87 6279.18,5130.2 6279.17,5130.52 6279.2,5130.84 6279.28,5131.17 6279.41,5131.5 6279.6,5131.85 6279.87,5132.21
  region net HTX0N: 6264.22,5096.59 6261.39,5099.41 6260.65,5098.8 6259.97,5098.47 6259.33,5098.37 6258.67,5098.42 6257.21,5098.73 6256.33,5098.85 6255.31,5098.86 6263.66,5090.51 6263.68,5091.04 6263.65,5091.53 6263.6,5091.98 6263.45,5092.8 6263.23,5093.87 6263.18,5094.2 6263.17,5094.52 6263.2,5094.84 6263.28,5095.17 6263.41,5095.5 6263.6,5095.85 6263.87,5096.21
  region net HTX0P: 6266.52,5104.02 6266.52,5108.02 6265.94,5108.09 6265.43,5108.31 6264.98,5108.65 6264.6,5109.09 6264.26,5109.63 6263.97,5110.24 6263.45,5111.63 6262.73,5113.86 6262.46,5114.58 6262.17,5115.26 6261.83,5115.89 6261.45,5116.44 6261.01,5116.91 6261.01,5105.09 6261.54,5105.37 6262.17,5105.4 6262.87,5105.24 6263.61,5104.97 6265.13,5104.34 6265.85,5104.11
  region net HTXCP: 6288.39,5059.59 6291.22,5062.41 6290.6,5063.15 6290.28,5063.83 6290.17,5064.48 6290.23,5065.13 6290.53,5066.59 6290.65,5067.47 6290.66,5068.49 6282.31,5060.14 6282.84,5060.13 6283.33,5060.15 6283.79,5060.2 6284.61,5060.35 6285.67,5060.58 6286,5060.62 6286.33,5060.63 6286.65,5060.6 6286.97,5060.53 6287.31,5060.4 6287.65,5060.2 6288.01,5059.93
  region net HTXCN: 6291.22,5051.59 6288.39,5054.41 6287.65,5053.8 6286.97,5053.47 6286.33,5053.37 6285.67,5053.42 6284.21,5053.73 6283.33,5053.85 6282.31,5053.86 6290.66,5045.51 6290.68,5046.04 6290.65,5046.53 6290.6,5046.98 6290.45,5047.8 6290.23,5048.87 6290.18,5049.2 6290.17,5049.52 6290.2,5049.84 6290.28,5050.17 6290.41,5050.5 6290.6,5050.85 6290.87,5051.21
  region net LCD0-D17: 5814.08,4914.5 5814.08,4909.5 5814.98,4909.42 5815.76,4909.21 5816.45,4908.87 5817.08,4908.44 5817.68,4907.92 5819.6,4906.09 5819.6,4917.91 5817.68,4916.08 5817.08,4915.56 5816.45,4915.13 5815.76,4914.79 5814.98,4914.58
  region net LCD0-D16: 5810.3,4965.28 5815.3,4965.28 5815.38,4966.18 5815.6,4966.96 5815.93,4967.65 5816.37,4968.28 5816.88,4968.88 5818.71,4970.79 5806.9,4970.79 5808.72,4968.88 5809.24,4968.28 5809.67,4967.65 5810.01,4966.96 5810.23,4966.18
  region net LCD0-D16: 4469.52,4568.5 4469.52,4573.5 4468.63,4573.58 4467.85,4573.79 4467.16,4574.13 4466.53,4574.56 4465.93,4575.08 4464.01,4576.91 4464.01,4565.09 4465.93,4566.92 4466.53,4567.44 4467.16,4567.87 4467.85,4568.21 4468.63,4568.42
  region net LCD0-D17: 4484.52,4552.5 4484.52,4557.5 4483.63,4557.58 4482.85,4557.79 4482.16,4558.13 4481.53,4558.56 4480.93,4559.08 4479.01,4560.91 4479.01,4549.09 4480.93,4550.92 4481.53,4551.44 4482.16,4551.87 4482.85,4552.21 4483.63,4552.42
  region net LCD0-D18: 4497.52,4536.5 4497.52,4541.5 4496.63,4541.58 4495.85,4541.79 4495.16,4542.13 4494.53,4542.56 4493.93,4543.08 4492.01,4544.91 4492.01,4533.09 4493.93,4534.92 4494.53,4535.44 4495.16,4535.87 4495.85,4536.21 4496.63,4536.42
  region net LCD0-D21: 4541.15,4492.81 4537.62,4496.35 4536.93,4495.77 4536.22,4495.37 4535.5,4495.12 4534.74,4494.98 4533.95,4494.92 4531.31,4494.86 4539.66,4486.51 4539.72,4489.15 4539.78,4489.94 4539.92,4490.69 4540.17,4491.42 4540.57,4492.12
  region net LCD0-D18: 5915.3,5088.28 5920.3,5088.28 5920.38,5089.18 5920.6,5089.96 5920.93,5090.65 5921.37,5091.28 5921.88,5091.88 5923.71,5093.79 5911.9,5093.79 5913.72,5091.88 5914.24,5091.28 5914.67,5090.65 5915.01,5089.96 5915.23,5089.18
  region net LCD0-D19: 5943.08,4855.5 5943.08,4850.5 5943.79,4850.62 5944.52,4850.92 5946.01,4851.75 5946.73,4852.12 5947.41,4852.36 5948.04,4852.37 5948.6,4852.09 5948.6,4863.91 5948.18,4863.46 5947.8,4862.94 5947.47,4862.35 5947.18,4861.71 5946.14,4858.91 5945.6,4857.61 5945.29,4857.03 5944.95,4856.52 5944.57,4856.1 5944.13,4855.77 5943.64,4855.57
  region net LCD0-D19: 5866.52,4850.5 5866.52,4855.5 5865.63,4855.58 5864.85,4855.79 5864.16,4856.13 5863.53,4856.56 5862.93,4857.08 5861.01,4858.91 5861.01,4847.09 5862.93,4848.92 5863.53,4849.44 5864.16,4849.87 5864.85,4850.21 5865.63,4850.42
  region net USB0-VBUSDET: 6909.1,6116.54 6913.34,6112.3 6913.96,6112.82 6914.62,6113.22 6915.33,6113.53 6916.08,6113.75 6916.86,6113.91 6918.47,6114.09 6919.3,6114.14 6910.94,6122.49 6910.82,6120.86 6910.71,6120.06 6910.55,6119.28 6910.33,6118.53 6910.03,6117.82 6909.62,6117.15
  region net SDC2-DS: 4889.52,4809.5 4889.52,4814.5 4888.63,4814.58 4887.85,4814.79 4887.16,4815.13 4886.53,4815.56 4885.93,4816.08 4884.01,4817.91 4884.01,4806.09 4885.93,4807.92 4886.53,4808.44 4887.16,4808.87 4887.85,4809.21 4888.63,4809.42
  region net SDC2-DS: 5713.3,5128.2 5718.3,5128.2 5718.38,5129.1 5718.6,5129.88 5718.93,5130.57 5719.37,5131.2 5719.88,5131.8 5721.71,5133.72 5709.9,5133.72 5711.72,5131.8 5712.24,5131.2 5712.67,5130.57 5713.01,5129.88 5713.23,5129.1
  region net VDD-SYSFB: 5791.64,5349.05 5798.71,5341.98 5799.15,5342.71 5799.32,5343.61 5799.32,5344.61 5799.21,5346.57 5799.31,5347.37 5799.64,5347.93 5800.29,5348.17 5791.97,5356.49 5791.98,5355.68 5792.26,5352.57 5792.3,5351.5 5792.24,5350.52 5792.03,5349.68
  region net GM0_LED2: 5766.68,4378.12 5770.92,4373.88 5771.47,4374.33 5771.95,4374.56 5772.41,4374.61 5772.87,4374.55 5773.91,4374.28 5774.54,4374.18 5775.29,4374.17 5766.97,4382.49 5766.98,4381.74 5767.08,4381.11 5767.35,4380.07 5767.41,4379.61 5767.36,4379.15 5767.13,4378.66
  region net GM0_LED1: 5792.8,4383.31 5798.8,4383.31 5798.87,4384.11 5799.05,4384.86 5799.34,4385.58 5799.71,4386.26 5800.14,4386.93 5801.15,4388.19 5801.69,4388.81 5789.92,4388.81 5790.98,4387.57 5791.46,4386.93 5791.9,4386.26 5792.27,4385.58 5792.56,4384.86 5792.74,4384.11
  region net GM0_LED1: 5599.37,3713.6 5595.12,3709.36 5595.64,3708.75 5596.04,3708.09 5596.35,3707.38 5596.57,3706.63 5596.73,3705.86 5596.91,3704.25 5596.97,3703.43 5605.29,3711.76 5603.67,3711.89 5602.87,3711.99 5602.09,3712.15 5601.35,3712.38 5600.64,3712.68 5599.98,3713.08
  region net GM0_LED2: 5576.37,3713.37 5572.12,3709.12 5572.64,3708.51 5573.04,3707.85 5573.35,3707.14 5573.57,3706.4 5573.73,3705.62 5573.91,3704.01 5573.97,3703.2 5582.29,3711.52 5580.67,3711.65 5579.87,3711.76 5579.09,3711.92 5578.35,3712.14 5577.64,3712.45 5576.98,3712.85
  region net CPUX-RX: 6263.8,5254 6263.8,5250 6264.3,5249.87 6264.71,5249.53 6265.05,5249.03 6265.34,5248.42 6265.91,5247.13 6266.23,5246.56 6266.61,5246.11 6266.61,5257.89 6266.23,5257.44 6265.91,5256.87 6265.34,5255.58 6265.05,5254.97 6264.71,5254.47 6264.3,5254.13
  region net CPUX-TX: 6245.83,5253.86 6248.66,5251.03 6249.06,5251.5 6250.32,5253.45 6250.77,5254.09 6251.25,5254.63 6251.76,5255 6252.29,5255.17 6243.97,5263.49 6243.98,5262.9 6244.08,5262.29 6244.26,5261.65 6244.75,5260.34 6245.91,5257.69 6246.15,5257.05 6246.32,5256.44 6246.43,5255.85 6246.45,5255.29 6246.37,5254.77 6246.17,5254.29
  region net CAN-TX0: 5090.77,6018.14 5087.95,6020.97 5087.18,6020.33 5086.45,6019.94 5085.71,6019.75 5084.95,6019.69 5083.29,6019.8 5082.35,6019.85 5081.31,6019.83 5089.64,6011.51 5089.65,6012.55 5089.53,6014.35 5089.5,6015.15 5089.51,6015.53 5089.55,6015.9 5089.63,6016.27 5089.75,6016.64 5089.91,6017.01 5090.14,6017.38 5090.42,6017.76
  region net CAN-RX0: 5069.77,6019.14 5066.95,6021.97 5066.18,6021.33 5065.45,6020.94 5064.71,6020.75 5063.95,6020.69 5062.29,6020.8 5061.35,6020.85 5060.31,6020.83 5068.64,6012.51 5068.65,6013.55 5068.53,6015.35 5068.5,6016.15 5068.51,6016.53 5068.55,6016.9 5068.63,6017.27 5068.75,6017.64 5068.91,6018.01 5069.14,6018.38 5069.42,6018.76
  region net IR-RX: 5047.48,6019.44 5043.24,6023.68 5042.63,6023.16 5041.97,6022.76 5041.26,6022.45 5040.51,6022.23 5039.74,6022.07 5038.13,6021.89 5037.31,6021.83 5045.64,6013.51 5045.77,6015.14 5045.87,6015.93 5046.03,6016.71 5046.26,6017.46 5046.56,6018.16 5046.96,6018.83
  region net USB0-VBUSDET: 5011.48,6020.44 5007.24,6024.68 5006.63,6024.16 5005.97,6023.76 5005.26,6023.45 5004.51,6023.23 5003.74,6023.07 5002.13,6022.89 5001.31,6022.83 5009.64,6014.51 5009.77,6016.14 5009.87,6016.93 5010.03,6017.71 5010.26,6018.46 5010.56,6019.16 5010.96,6019.83
  region net USB0-DRVVBUS: 4988.48,6020.44 4984.24,6024.68 4983.63,6024.16 4982.97,6023.76 4982.26,6023.45 4981.51,6023.23 4980.74,6023.07 4979.13,6022.89 4978.31,6022.83 4986.64,6014.51 4986.77,6016.14 4986.87,6016.93 4987.03,6017.71 4987.26,6018.46 4987.56,6019.16 4987.96,6019.83
  region net CAN-TX0: 7045.12,4462 7045.12,4458 7046.11,4457.91 7046.9,4457.67 7047.56,4457.28 7048.14,4456.79 7049.24,4455.54 7049.86,4454.84 7050.61,4454.11 7050.61,4465.89 7049.86,4465.16 7048.68,4463.8 7048.14,4463.21 7047.86,4462.95 7047.56,4462.72 7047.25,4462.51 7046.9,4462.33 7046.53,4462.19 7046.11,4462.09 7045.64,4462.02
  region net CAN-RX0: 7204.8,4317.69 7200.8,4317.69 7200.72,4316.7 7200.47,4315.9 7200.09,4315.24 7199.59,4314.66 7198.34,4313.57 7197.64,4312.94 7196.92,4312.19 7208.69,4312.19 7207.97,4312.94 7206.61,4314.12 7206.02,4314.66 7205.76,4314.94 7205.52,4315.24 7205.31,4315.55 7205.14,4315.9 7205,4316.28 7204.89,4316.7 7204.83,4317.17
  region net IR-RX: 7035.48,4099.44 7031.24,4103.68 7030.63,4103.16 7029.97,4102.76 7029.26,4102.45 7028.51,4102.23 7027.74,4102.07 7026.13,4101.89 7025.31,4101.83 7033.64,4093.51 7033.77,4095.14 7033.87,4095.93 7034.03,4096.71 7034.26,4097.46 7034.56,4098.16 7034.96,4098.83
  region net USB0-DRVVBUS: 6990.37,6033.68 6986.12,6029.44 6986.64,6028.83 6987.04,6028.16 6987.35,6027.46 6987.57,6026.71 6987.73,6025.93 6987.91,6024.33 6987.97,6023.51 6996.29,6031.83 6994.67,6031.96 6993.87,6032.07 6993.09,6032.23 6992.35,6032.45 6991.64,6032.76 6990.98,6033.16
  region net PWRON: 4247.37,5380.68 4243.12,5376.44 4243.64,5375.83 4244.04,5375.16 4244.35,5374.46 4244.57,5373.71 4244.73,5372.93 4244.91,5371.33 4244.97,5370.51 4253.29,5378.83 4251.67,5378.96 4250.87,5379.07 4250.09,5379.23 4249.35,5379.45 4248.64,5379.76 4247.98,5380.16
Inner5:
  drawing of 158 lines, arcs and shapes, not listed
GND2:
  region net HP-DET: 5499.5,5711.46 5495.26,5715.7 5494.65,5715.18 5493.99,5714.78 5493.27,5714.47 5492.53,5714.25 5491.75,5714.09 5490.13,5713.91 5489.31,5713.86 5497.66,5705.51 5497.79,5707.14 5497.9,5707.94 5498.05,5708.72 5498.28,5709.47 5498.58,5710.18 5498.99,5710.85
  region net HBIAS: 5485.34,5722.46 5478.27,5729.54 5477.63,5728.95 5476.91,5728.43 5476.13,5728.04 5475.31,5727.86 5483.66,5719.51 5483.84,5720.33 5484.23,5721.11 5484.75,5721.82
  region net HPOUTL: 5466.92,5731.04 5459.85,5738.12 5458.31,5736.43 5457.82,5735.95 5457.31,5735.53 5456.74,5735.2 5456.08,5734.97 5455.31,5734.86 5463.66,5726.51 5463.78,5727.28 5464.01,5727.94 5464.34,5728.51 5464.75,5729.02 5465.23,5729.5
  region net HPOUTFB: 5442.92,5732.04 5435.85,5739.12 5434.31,5737.43 5433.82,5736.95 5433.31,5736.53 5432.74,5736.2 5432.08,5735.97 5431.31,5735.86 5439.66,5727.51 5439.78,5728.28 5440.01,5728.94 5440.34,5729.51 5440.75,5730.02 5441.23,5730.5
  region net HPOUTR: 5414.8,5731.72 5404.8,5731.72 5404.91,5729.43 5404.91,5728.75 5404.84,5728.1 5404.66,5727.46 5404.36,5726.84 5403.9,5726.21 5415.71,5726.21 5415.24,5726.84 5414.94,5727.46 5414.77,5728.1 5414.7,5728.75 5414.7,5729.43
  region net HP-DET: 5939.1,6252.54 5943.34,6248.3 5943.96,6248.82 5944.62,6249.22 5945.33,6249.53 5946.08,6249.75 5946.86,6249.91 5948.47,6250.09 5949.3,6250.14 5940.94,6258.49 5940.82,6256.86 5940.71,6256.06 5940.55,6255.28 5940.33,6254.53 5940.03,6253.82 5939.62,6253.15
  region net HBIAS: 5834.8,6187.28 5844.8,6187.28 5844.7,6189.57 5844.7,6190.25 5844.77,6190.9 5844.94,6191.54 5845.24,6192.16 5845.71,6192.79 5833.9,6192.79 5834.36,6192.16 5834.66,6191.54 5834.84,6190.9 5834.91,6190.25 5834.91,6189.57
  region net HPOUTL: 5804.69,6173.96 5811.76,6166.88 5813.3,6168.57 5813.78,6169.05 5814.3,6169.47 5814.87,6169.8 5815.52,6170.03 5816.3,6170.14 5807.94,6178.49 5807.83,6177.72 5807.6,6177.06 5807.27,6176.49 5806.86,6175.98 5806.38,6175.5
  region net HPOUTFB: 5776.69,6183.96 5783.76,6176.88 5785.3,6178.57 5785.78,6179.05 5786.3,6179.47 5786.87,6179.8 5787.52,6180.03 5788.3,6180.14 5779.94,6188.49 5779.83,6187.72 5779.6,6187.06 5779.27,6186.49 5778.86,6185.98 5778.38,6185.5
  region net HPOUTR: 5738.69,6174.96 5745.76,6167.88 5747.3,6169.57 5747.78,6170.05 5748.3,6170.47 5748.87,6170.8 5749.52,6171.03 5750.3,6171.14 5741.94,6179.49 5741.83,6178.72 5741.6,6178.06 5741.27,6177.49 5740.86,6176.98 5740.38,6176.5
Bottom Layer:
  drawing of 640 lines, arcs and shapes, not listed

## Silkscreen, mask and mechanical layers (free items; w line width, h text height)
Bottom Silkscreen Layer:
  circle w20: c3744.8,4980 r27
  circle w20: c6957.8,4528 r27
  text "BIOS" at 5677.03,6127.99 h29.2
  text "TFCard/JTAG" at 6771.12,6031 h38.94 r90
  text "Avaota A1" at 4870.8,5548 h270
  text "OV13850" at 7031.12,5244.16 h38.94 r90
  text "RGB888/LVDS/MIPI DSI/JTAG /  UART/IIC/I2S/SPI/PWM  MUX" at 3721.12,4989.1 h43.41 r90
  text "v1.3" at 7187.98,3724.24 h38.94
